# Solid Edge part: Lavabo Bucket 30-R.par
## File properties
Title: LAVABO BUCKET 30 R
Author: DESYS
Template: Iso Part.par
Last saved by: PIM_1
Revision: 54
Application: Solid Edge
Tipo di contenuto documento: 0
Accuracy: 0,990
Document Number: 8802
Revision: 0
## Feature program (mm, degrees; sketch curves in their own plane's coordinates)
lofted protrusion "unnamed LoftedProtrusion 1"
sketch for "ScavoEstrusione_2" plane through (0, 0, 235) normal (0, 0, 1) x-axis (1, 0, 0)
  circle centre (0, 0) radius 120
extrude "ScavoEstrusione_2" cut finite 86 along -normal  Treatment1_DraftAngle = 13.5 deg
sketch for "ScavoEstrusione_3" plane through (0, 0, 0) normal (0, 0, -1) x-axis (0, 1, 0)
  circle centre (0, 0) radius 77.5
extrude "ScavoEstrusione_3" cut finite 104 along -normal
sketch for "ScavoEstrusione_5" plane through (0, 0, 149) normal (0, 0, 1) x-axis (1, 0, 0)
  circle centre (0, 0) radius 20
extrude "ScavoEstrusione_5" cut finite 455 along -normal
fillet "Rotondo_1" radius 10
sketch for "ProtrusioneEstrusa_1" #1 plane through (0, 0, 104) normal (0, 0, -1) x-axis (-1, 0, 0)
  circle centre (0, 0) radius 32.5
sketch for "ProtrusioneEstrusa_1" #2 plane through (0, 0, 104) normal (0, 0, -1) x-axis (-1, 0, 0)
  circle centre (0, 0) radius 20
extrude "ProtrusioneEstrusa_1" add finite 35 along +normal
sketch for "ScavoEstrusione_8" #1 plane through (0, -132.5, 117.5) normal (0, -0.98909, -0.147311) x-axis (0, -0.147311, 0.98909)
  circle centre (78.796, 0) radius 5
sketch for "ScavoEstrusione_8" #2 plane through (0, -132.5, 117.5) normal (0, -0.98909, -0.147311) x-axis (0, -0.147311, 0.98909)
  circle centre (-1889.0299, 79.6634) radius 5
extrude "ScavoEstrusione_8" cut finite 5 along -normal
fillet "Rotondo_2" radius 20
fillet "Rotondo_3" radius 10
fillet "Rotondo_4" radius 5
fillet "Rotondo_5" radius 0.5
fillet "Rotondo_6" radius 5
fillet "Rotondo_7" radius 2
fillet "Rotondo_8" radius 2
sketch for "ProtrusioneEstrusa_4" plane through (260, 19.9, 19.9) normal (1, 0, 0) x-axis (0, 1, 0)
  line (-117.4, 180.1) -> (77.6, 180.1)
  line (77.6, 180.1) -> (60.1, -19.9)
  line (60.1, -19.9) -> (-99.9, -19.9)
  line (-99.9, -19.9) -> (-117.4, 180.1)
  dimension (linear) = 60.1
extrude "ProtrusioneEstrusa_4" add through along -normal  Profile_Plane1_Distance = 260 mm
sketch for "unnamed Cutout 1" plane through (74.6552, 0, 0) normal (0, 0, -1) x-axis (0, -1, 0)
  line (-50, -72.5607) -> (-50, -150.3448)
  line (50, -150.3448) -> (-50, -150.3448)
  line (50, -72.5607) -> (50, -150.3448)
  arc centre (0, 74.6552) radius 155.4751 from (50, -72.5607) to (-50, -72.5607) cw
extrude "unnamed Cutout 1" cut along +normal
sketch for "unnamed Cutout 2" plane through (74.6552, 0, 0) normal (0, 0, -1) x-axis (0, -1, 0)
  line (-50, 15.4416) -> (-50, -63.3573)
  line (50, -63.3573) -> (50, 15.4416)
extrude "unnamed Cutout 2" cut along +normal
delete blends "unnamed DeleteBlends 1"
draft "Spoglia_1"  Angles1 = 3 deg
sketch for "unnamed Cutout 3" plane through (260, 0, 100) normal (1, 0, 0) x-axis (0, -1, 0)
extrude "unnamed Cutout 3" cut through along -normal
mirror "unnamed Mirror 1" of "ScavoEstrusione_8", "Rotondo_5"
pattern "unnamed Pattern 1"
sketch for "unnamed Cutout 4" plane through (183.5189, 0, 200) normal (0, 0, 1) x-axis (-1, 0, 0)
  circle centre (-18.742, 0) radius 20
extrude "unnamed Cutout 4" cut through along -normal
fillet "Rotondo_10" radius 5
fillet "Rotondo_11" radius 5
fillet "Rotondo_12" radius 5
fillet "Rotondo_13" radius 5
fillet "Rotondo_14" radius 5
fillet "Rotondo_15" radius 5
fillet "Rotondo_16" radius 2
fillet "Rotondo_17" radius 2
sketch for "ScavoEstrusione_15" plane through (72.1552, 0, 0) normal (0, 0, -1) x-axis (-1, 0, 0)
  circle centre (170.1877, 3.5743) radius 7.5
extrude "ScavoEstrusione_15" cut finite 70 along -normal
sketch for "unnamed Cutout 5" #1 plane through (260, 0, 100) normal (1, 0, 0) x-axis (0, 1, 0)
  circle centre (-20, 26.0948) radius 7.5
sketch for "unnamed Cutout 5" #2 plane through (260, 0, 100) normal (1, 0, 0) x-axis (0, 1, 0)
  circle centre (20, 26.0948) radius 7.5
sketch for "unnamed Cutout 5" #3 plane through (260, 0, 100) normal (1, 0, 0) x-axis (0, 1, 0)
  circle centre (-74.9809, 84.4918) radius 7.5
sketch for "unnamed Cutout 5" #4 plane through (260, 0, 100) normal (1, 0, 0) x-axis (0, 1, 0)
  circle centre (72.8243, 84.4918) radius 7.5
extrude "unnamed Cutout 5" cut finite 70 along -normal
fillet "unnamed Round 1"
sketch for "ProtrusioneEstrusa_5" plane through (16.3476, 0, 104) normal (0, 0, -1) x-axis (1, 0, 0)
extrude "ProtrusioneEstrusa_5" add finite 35 along +normal
sketch for "unnamed Cutout 6" plane through (0, 0, 69) normal (0, 0, -1) x-axis (0, -1, 0)
extrude "unnamed Cutout 6" cut finite 420 along -normal
fillet "unnamed Round 2"
sketch for "ScavoEstrusione_18" plane through (23.3996, -230, 23.3996) normal (0, -1, 0) x-axis (1, 0, 0)
extrude "ScavoEstrusione_18" cut finite 100 along -normal  Profile_Plane1_Distance = 230 mm
sketch for "ScavoEstrusione_20" plane through (14.9758, 230, 14.9758) normal (0, 1, 0) x-axis (-1, 0, 0)
extrude "ScavoEstrusione_20" cut finite 100 along -normal  Profile_Plane1_Distance = 230 mm
fillet "unnamed Round 3"
Other named dimensions: "SuperficieOffset_2": Distance = 10 mm
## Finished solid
Body 1: sheet body, 1 face, 4 edges, 4 vertices.
  Faces by surface: plane 1
  Edges by curve: line 3, circle 1
Body 2: sheet body, 3 faces, 3 edges, 0 vertices.
  Faces by surface: cone 1, plane 1, torus 1
  Edges by curve: circle 3
Body 3: solid body, 92 faces, 173 edges, 80 vertices.
  Faces by surface: cylinder 28, plane 22, torus 20, blend 15, sphere 4, cone 3
  Edges by curve: circle 78, intersection 43, line 43, ellipse 9
Bounding box of the edges (mm; curved faces can reach further): 422.837 x 325.673 x 235.000, from (-162.8365, -162.8365, -0.0003) to (260, 162.8365, 235).
Cylindrical faces by radius (mm): R2 x1, R5 x16, R7.5 x5, R20 x2, R25 x2, R146.7905 x1, R155.4751 x1
Conical faces (half-angle, radius in mm at the cone's reference point): 3 deg R77.5 x1, 8.4711 deg R150 x1, 13.5 deg R120 x1, 13.5 deg R163.7566 x1
Toroidal faces (ring radius, tube radius in mm): R9.5 r2 x6, R22 r2 x1, R23 r2 x1, R25 r5 x1, R30 r5 x2, R30 r10 x1, R67.3048 r5 x1, R82.2448 r5 x1, R83.5865 r20 x1, R83.5865 r65 x2, R110.6895 r5 x1, R123.9417 r5 x1, R144.2002 r5 x1, R150.5871 r5 x1
Spherical faces by radius (mm): R5 x4
Planar faces by outward normal: +x 3, +y 1, +z 3, -x 1, -y 1, -z 5, oblique 8
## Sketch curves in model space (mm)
line (249.1456, 0, 205) -> (248.4952, 0, 0)
arc centre (0.0501, -1.5533, 205) radius 149.2002 from (105.4081, 104.0894, 205) through (136.7593, 58.2069, 205) to (149.1456, 4.0342, 205)
line (105.4081, 104.0894, 205) -> (249.1456, 104.0342, 205)
line (249.1456, 104.0342, 205) -> (249.1456, -95.9658, 205)
line (105.7085, -105.292, 205) -> (249.1456, -95.9658, 205)
arc centre (0, 0, 205) radius 149.2002 from (105.7085, -105.292, 205) through (138.6568, -55.0907, 205) to (149.1456, 4.0342, 205)
arc centre (0, 0, 0) radius 115.635 from (83.4952, -80, 0) through (115.635, 0, 0) to (83.4952, 80, 0)
line (248.4952, 80, 0) -> (83.4952, 80, 0)
line (248.4952, 80, 0) -> (248.4952, -80, 0)
line (248.4952, -80, 0) -> (83.4952, -80, 0)
line (-115, 0, 0) -> (-150, 0, 235)
line (150, 0, 235) -> (115, 0, 0)
circle centre (0, 0, 235) radius 150
circle centre (0, 0, 0) radius 115
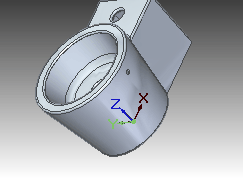
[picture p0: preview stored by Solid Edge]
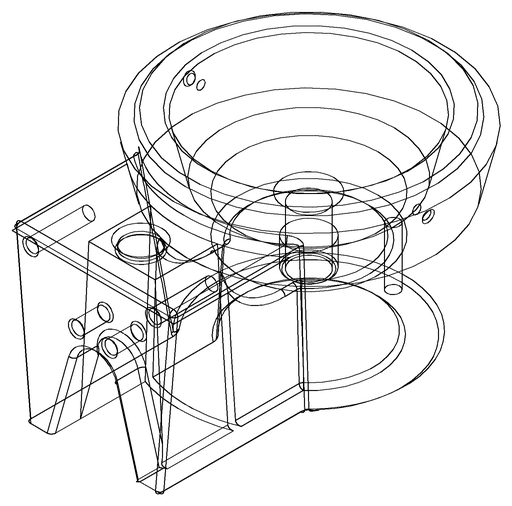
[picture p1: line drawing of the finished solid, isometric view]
